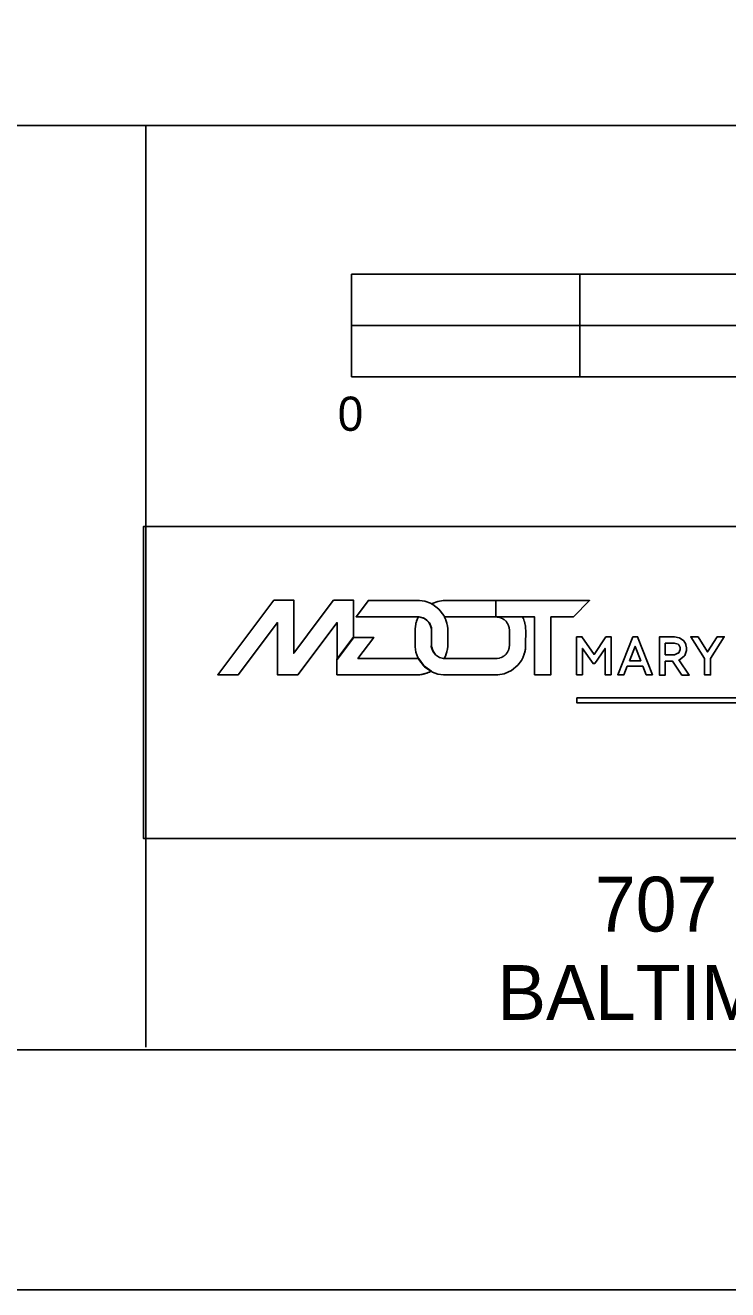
# Model space of a CAD drawing. Extents: x -1 to 9.2, y 0 to 14.8.
# Drawn here: x 2.774 to 3.799, y 0 to 1.846 of the extents above; entities that cross this region are included whole.
import ezdxf

# ---------------------------------------------------------------- set-up
doc = ezdxf.new("R2010")
doc.units = 0
for name, color, linetype in [('BORD-LINE', 7, 'Continuous'), ('BORD-SCAL', 7, 'Continuous'), ('MSHA-LOGO', 7, 'Continuous'), ('USER-LINE', 7, 'Continuous'), ('USER-PAGE', 7, 'Continuous')]:
    doc.layers.add(name, color=color, linetype=linetype)

msp = doc.modelspace()

# ---------------------------------------------------------------- linework, layer by layer
at = {"layer": 'BORD-LINE'}
for p, q in [((0.35, 1.7), (8.15, 1.7)), ((2.95, 0.354), (2.95, 1.7))]:
    msp.add_line(p, q, dxfattribs=at)
msp.add_lwpolyline([(0.35, 0.8607), (0.35, 0.35), (8.15, 0.35), (8.15, 10.65), (0.35, 10.65), (0.35, 0.8607)], dxfattribs=at)
at = {"layer": 'BORD-SCAL'}
for p, q in [((3.25, 1.333), (3.25, 1.483)), ((5.25, 1.483), (3.25, 1.483)), ((5.25, 1.483), (3.25, 1.483)), ((3.583, 1.333), (3.583, 1.483)), ((4.25, 1.408), (3.25, 1.408)), ((5.25, 1.333), (3.25, 1.333)), ((5.25, 1.333), (3.25, 1.333))]:
    msp.add_line(p, q, dxfattribs=at)
for points in [[(3.583, 1.483), (3.917, 1.483), (3.917, 1.408), (3.583, 1.408)], [(3.25, 1.333), (3.583, 1.333), (3.583, 1.408), (3.25, 1.408)]]:
    msp.add_lwpolyline(points, close=True, dxfattribs=at)
at = {"layer": 'MSHA-LOGO'}
for points in [[(3.2291, 0.9203), (3.2529, 0.952), (3.2529, 1.0068), (3.224, 1.0068), (3.206, 0.9829), (3.1658, 0.9294), (3.1658, 1.0068), (3.1369, 1.0068), (3.055, 0.898), (3.0849, 0.898), (3.142, 0.974), (3.142, 0.898), (3.172, 0.898), (3.2291, 0.974)], [(3.3477, 0.9824), (3.3484, 0.9824), (3.3551, 0.9806), (3.3557, 0.9803), (3.3564, 0.9799), (3.3597, 0.9775), (3.3626, 0.9746), (3.363, 0.974), (3.3636, 0.9732), (3.3655, 0.9691), (3.3666, 0.9647), (3.3667, 0.9637), (3.3667, 0.9637), (3.3667, 0.9636), (3.3667, 0.9636), (3.3667, 0.9634), (3.3667, 0.9628), (3.3667, 0.9627), (3.3667, 0.942), (3.3667, 0.9418), (3.3667, 0.9413), (3.3667, 0.9411), (3.3667, 0.9411), (3.3667, 0.941), (3.3667, 0.941), (3.3667, 0.9405), (3.3665, 0.9395), (3.3665, 0.9392), (3.3668, 0.9375), (3.3687, 0.9325), (3.3728, 0.9271), (3.3787, 0.9232), (3.3841, 0.9215), (3.3853, 0.9214), (3.3855, 0.9218), (3.3857, 0.922), (3.3857, 0.922), (3.3858, 0.9224), (3.3876, 0.9262), (3.3878, 0.9266), (3.3879, 0.9271), (3.3892, 0.9312), (3.3893, 0.9316), (3.3893, 0.9319), (3.3898, 0.934), (3.3899, 0.9342), (3.39, 0.9348), (3.3906, 0.9403), (3.3906, 0.9422), (3.3906, 0.9624), (3.3906, 0.9644), (3.39, 0.9697), (3.3899, 0.9704), (3.3898, 0.9706), (3.3893, 0.9727), (3.3893, 0.9729), (3.3892, 0.9733), (3.3879, 0.9775), (3.3878, 0.9779), (3.3876, 0.9783), (3.3858, 0.9822), (3.3857, 0.9826), (3.3846, 0.9846), (3.3776, 0.9935), (3.3687, 1.0005), (3.3667, 1.0016), (3.3652, 1.0023), (3.3571, 1.0052), (3.3492, 1.0064), (3.3466, 1.0064), (3.2747, 1.0064), (3.2568, 0.9826), (3.3466, 0.9826), (3.3467, 0.9825), (3.3474, 0.9824)], [(3.3858, 0.9823), (3.3862, 0.9823), (3.3864, 0.9823), (3.4601, 0.9823), (3.4602, 0.9823), (3.4605, 0.9823), (3.4605, 0.9823), (3.4607, 0.9826), (3.4607, 1.0062), (3.4607, 1.0062), (3.4602, 1.0062), (3.4601, 1.0062), (3.3864, 1.0062), (3.3838, 1.0062), (3.3759, 1.0049), (3.3679, 1.0021), (3.3667, 1.0016), (3.3687, 1.0005), (3.3776, 0.9935), (3.3846, 0.9846), (3.3857, 0.9826)], [(3.4607, 1.0062), (3.4607, 0.9824), (3.5172, 0.9824), (3.5172, 0.898), (3.5409, 0.898), (3.5409, 0.9824), (3.5739, 0.9824), (3.5975, 1.0061), (3.5975, 1.0062)], [(3.3671, 0.9028), (3.367, 0.9028), (3.3668, 0.903), (3.3668, 0.903), (3.3658, 0.9035), (3.3568, 0.9102), (3.356, 0.911), (3.3552, 0.9118), (3.3487, 0.9207), (3.3481, 0.9217), (3.348, 0.9217), (3.3478, 0.9217), (3.3477, 0.9217), (3.3474, 0.9217), (3.3468, 0.9217), (3.3466, 0.9217), (3.2594, 0.9217), (3.2826, 0.9523), (3.2527, 0.9523), (3.2289, 0.9208), (3.2289, 0.8979), (3.3465, 0.8979), (3.3471, 0.8979), (3.349, 0.898), (3.3492, 0.898), (3.3498, 0.898), (3.3515, 0.8983), (3.3517, 0.8983), (3.3519, 0.8983), (3.3524, 0.8985), (3.3525, 0.8985), (3.3526, 0.8985), (3.354, 0.8987), (3.3542, 0.8988), (3.3544, 0.8988), (3.3549, 0.8989), (3.3551, 0.8989), (3.3552, 0.899), (3.3564, 0.8992), (3.3566, 0.8992), (3.3566, 0.8993), (3.3574, 0.8995), (3.3575, 0.8995), (3.3576, 0.8996), (3.3587, 0.8999), (3.3588, 0.9), (3.3589, 0.9), (3.3596, 0.9002), (3.3597, 0.9003), (3.3598, 0.9003), (3.361, 0.9007), (3.3611, 0.9007), (3.3612, 0.9008), (3.3619, 0.901), (3.362, 0.901), (3.3621, 0.9011), (3.3634, 0.9016), (3.3635, 0.9016), (3.3636, 0.9017), (3.3642, 0.9019), (3.3642, 0.9019), (3.3644, 0.902), (3.3662, 0.9029), (3.3664, 0.903), (3.3665, 0.9029), (3.3669, 0.9028)], [(3.5784, 0.9534), (3.5862, 0.9534), (3.604, 0.9275), (3.6213, 0.9534), (3.6288, 0.9534), (3.6288, 0.8979), (3.6201, 0.8979), (3.6201, 0.9364), (3.6049, 0.9143), (3.6026, 0.9143), (3.587, 0.9364), (3.587, 0.8979), (3.5784, 0.8979)], [(3.6607, 0.9534), (3.6674, 0.9534), (3.6892, 0.8979), (3.68, 0.8979), (3.6751, 0.9102), (3.6524, 0.9102), (3.6475, 0.8979), (3.6386, 0.8979)], [(3.6993, 0.8976), (3.6993, 0.9531), (3.7189, 0.9531), (3.7213, 0.9531), (3.728, 0.9519), (3.7287, 0.9517), (3.7293, 0.9515), (3.7344, 0.9481), (3.7347, 0.9477), (3.7351, 0.9472), (3.7377, 0.9427), (3.7379, 0.9422), (3.738, 0.9417), (3.7388, 0.9371), (3.7388, 0.9356), (3.7388, 0.9331), (3.7364, 0.9262), (3.7359, 0.9255), (3.7354, 0.9248), (3.7287, 0.9197), (3.7278, 0.9195), (3.7428, 0.8973), (3.7321, 0.8973), (3.7186, 0.9177), (3.7079, 0.9177), (3.7079, 0.8973), (3.6993, 0.8973)], [(3.7079, 0.9442), (3.7079, 0.9272), (3.7192, 0.9272), (3.7211, 0.9272), (3.7264, 0.9292), (3.7269, 0.9295), (3.7274, 0.9299), (3.7298, 0.9346), (3.7298, 0.9361), (3.7298, 0.9377), (3.7277, 0.9418), (3.7272, 0.9422), (3.7268, 0.9425), (3.7209, 0.9442), (3.7189, 0.9442)], [(3.7739, 0.9217), (3.7739, 0.8976), (3.7652, 0.8976), (3.7652, 0.9217), (3.7451, 0.9534), (3.7557, 0.9534), (3.7696, 0.9313), (3.7837, 0.9534), (3.794, 0.9534)], [(3.6558, 0.9183), (3.6722, 0.9183), (3.6639, 0.9393)], [(3.5786, 0.8643), (5.4382, 0.8643), (5.4382, 0.8571), (3.5786, 0.8571)]]:
    msp.add_lwpolyline(points, close=True, dxfattribs=at)
for points in [[(3.3667, 0.9511), (3.3667, 0.9624), (3.3667, 0.9627), (3.3667, 0.9634), (3.3667, 0.9636), (3.3667, 0.964), (3.3668, 0.965), (3.3668, 0.9654), (3.3667, 0.9662), (3.3638, 0.9735), (3.3633, 0.9741), (3.3629, 0.9748), (3.36, 0.9778), (3.3566, 0.9802), (3.3558, 0.9806), (3.3552, 0.9809), (3.3485, 0.9827), (3.3478, 0.9827), (3.3478, 0.9826), (3.3477, 0.9824), (3.3474, 0.9818), (3.345, 0.9759), (3.3448, 0.9753), (3.3447, 0.9751), (3.3441, 0.973), (3.3441, 0.9728), (3.3439, 0.9719), (3.3429, 0.9648), (3.3429, 0.9624), (3.3429, 0.9511), (3.3429, 0.9499)], [(3.5043, 0.9624), (3.5043, 0.963), (3.5041, 0.9647), (3.5041, 0.9649), (3.5041, 0.9651), (3.5041, 0.9657), (3.5041, 0.9661), (3.504, 0.9672), (3.504, 0.9675), (3.504, 0.9676), (3.504, 0.9679), (3.504, 0.9679), (3.504, 0.968), (3.504, 0.9682), (3.504, 0.9682), (3.5039, 0.9684), (3.5037, 0.9699), (3.5036, 0.9701), (3.5036, 0.9702), (3.5035, 0.9705), (3.5035, 0.9707), (3.5035, 0.9708), (3.5031, 0.9725), (3.5031, 0.9726), (3.5031, 0.9728), (3.5031, 0.9729), (3.503, 0.9731), (3.5024, 0.9754), (3.5023, 0.9756), (3.5022, 0.976), (3.5008, 0.9798), (3.5006, 0.9801), (3.5006, 0.9803), (3.4997, 0.9822), (3.4996, 0.9824), (3.4996, 0.9825), (3.4994, 0.9827), (3.4613, 0.9827), (3.4612, 0.9824), (3.4616, 0.9824), (3.4618, 0.9824), (3.4619, 0.9824), (3.4624, 0.9823), (3.4625, 0.9823), (3.4628, 0.9822), (3.4659, 0.9816), (3.4661, 0.9815), (3.4664, 0.9814), (3.4689, 0.9806), (3.4691, 0.9805), (3.4693, 0.9804), (3.4706, 0.9796), (3.4708, 0.9796), (3.4709, 0.9796), (3.4709, 0.9796), (3.4711, 0.9795), (3.4723, 0.9787), (3.4725, 0.9786), (3.4726, 0.9785), (3.4726, 0.9785), (3.4727, 0.9784), (3.4738, 0.9776), (3.474, 0.9774), (3.4741, 0.9773), (3.4742, 0.9772), (3.4751, 0.9763), (3.4752, 0.9762), (3.4753, 0.9761), (3.4753, 0.9761), (3.4755, 0.9759), (3.4755, 0.9759), (3.4762, 0.9751), (3.4762, 0.975), (3.4764, 0.9749), (3.4764, 0.9748), (3.4766, 0.9745), (3.4767, 0.9744), (3.4767, 0.9744), (3.4774, 0.9734), (3.4774, 0.9734), (3.4775, 0.9733), (3.4777, 0.9728), (3.4777, 0.9728), (3.4778, 0.9726), (3.4779, 0.9726), (3.4779, 0.9725), (3.4783, 0.9718), (3.4783, 0.9717), (3.4784, 0.9716), (3.4786, 0.971), (3.4786, 0.971), (3.4787, 0.9709), (3.479, 0.97), (3.4791, 0.9699), (3.4791, 0.9699), (3.4792, 0.9693), (3.4792, 0.9692), (3.4793, 0.969), (3.4794, 0.969), (3.4794, 0.9689), (3.4797, 0.9683), (3.4797, 0.9681), (3.4797, 0.968), (3.4799, 0.9671), (3.48, 0.967), (3.48, 0.9668), (3.4801, 0.9663), (3.4801, 0.9661), (3.4802, 0.966), (3.4803, 0.9652), (3.4803, 0.9649), (3.4803, 0.9647), (3.4804, 0.9643), (3.4804, 0.9642), (3.4804, 0.9637), (3.4806, 0.9626), (3.4806, 0.9622), (3.4806, 0.9416), (3.4806, 0.9411), (3.4805, 0.9398), (3.4804, 0.9396), (3.4804, 0.9394), (3.4803, 0.9389), (3.4803, 0.9389), (3.4803, 0.9386), (3.4801, 0.9379), (3.4801, 0.9377), (3.4801, 0.9374), (3.48, 0.9369), (3.48, 0.9368), (3.4799, 0.9367), (3.4797, 0.9358), (3.4797, 0.9357), (3.4797, 0.9356), (3.4794, 0.9349), (3.4794, 0.9348), (3.4794, 0.9347), (3.4793, 0.9345), (3.4792, 0.9345), (3.4791, 0.934), (3.4791, 0.9339), (3.479, 0.9338), (3.4787, 0.933), (3.4786, 0.9328), (3.4786, 0.9328), (3.4784, 0.9322), (3.4783, 0.9321), (3.4783, 0.932), (3.4779, 0.9312), (3.4779, 0.9312), (3.4778, 0.931), (3.4777, 0.931), (3.4777, 0.931), (3.4775, 0.9305), (3.4774, 0.9304), (3.4774, 0.9303), (3.4767, 0.9294), (3.4767, 0.9294), (3.4766, 0.9293), (3.4764, 0.929), (3.4764, 0.9289), (3.4762, 0.9288), (3.4761, 0.9287), (3.4755, 0.9279), (3.4755, 0.9279), (3.4753, 0.9277), (3.4752, 0.9276), (3.4752, 0.9276), (3.4751, 0.9275), (3.4742, 0.9266), (3.4741, 0.9265), (3.474, 0.9264), (3.4738, 0.9263), (3.4727, 0.9254), (3.4726, 0.9253), (3.4725, 0.9252), (3.4725, 0.9251), (3.4723, 0.9251), (3.4711, 0.9243), (3.4709, 0.9242), (3.4708, 0.9242), (3.4708, 0.9242), (3.4707, 0.9242), (3.4693, 0.9234), (3.4691, 0.9233), (3.4689, 0.9232), (3.4664, 0.9224), (3.4661, 0.9223), (3.4658, 0.9222), (3.4628, 0.9216), (3.4625, 0.9215), (3.4623, 0.9215), (3.4618, 0.9214), (3.4618, 0.9214), (3.4615, 0.9214), (3.4609, 0.9214), (3.4607, 0.9214), (3.387, 0.9214), (3.3867, 0.9214), (3.3861, 0.9214), (3.386, 0.9214), (3.3841, 0.9215), (3.3787, 0.9232), (3.3728, 0.9272), (3.3687, 0.9331), (3.3671, 0.9384), (3.367, 0.9402), (3.367, 0.9405), (3.367, 0.9412), (3.367, 0.9414), (3.367, 0.9511), (3.3667, 0.9511)], [(3.3429, 0.9499), (3.3429, 0.9414), (3.3429, 0.9388), (3.3441, 0.931), (3.3469, 0.9229), (3.3477, 0.9214), (3.3482, 0.9204), (3.3549, 0.9112), (3.3557, 0.9104), (3.3564, 0.9096), (3.3656, 0.9029), (3.3667, 0.9024), (3.3682, 0.9016), (3.3762, 0.8988), (3.3841, 0.8976), (3.3867, 0.8976), (3.4604, 0.8976), (3.4635, 0.8976), (3.4726, 0.8993), (3.4835, 0.9042), (3.4926, 0.9117), (3.4981, 0.9188), (3.4994, 0.9214), (3.4995, 0.9216), (3.5004, 0.9234), (3.5005, 0.9236), (3.5006, 0.924), (3.502, 0.9278), (3.5021, 0.9282), (3.5022, 0.9284), (3.5029, 0.9307), (3.5029, 0.9309), (3.5029, 0.931), (3.5029, 0.9312), (3.5029, 0.9313), (3.5033, 0.933), (3.5033, 0.9331), (3.5033, 0.9333), (3.5035, 0.9336), (3.5035, 0.9337), (3.5035, 0.9339), (3.5038, 0.9354), (3.5038, 0.9355), (3.5038, 0.9356), (3.5038, 0.9358), (3.5038, 0.9358), (3.5038, 0.936), (3.5038, 0.9362), (3.5038, 0.9363), (3.5038, 0.9368), (3.504, 0.9378), (3.504, 0.9381), (3.504, 0.9387), (3.504, 0.9389), (3.504, 0.9395), (3.5041, 0.9409), (3.5041, 0.9414), (3.5043, 0.9624)]]:
    msp.add_lwpolyline(points, dxfattribs=at)
at = {"layer": 'USER-LINE'}
msp.add_lwpolyline([(5.5468, 0.6588), (2.9468, 0.6588), (2.9468, 1.1144), (5.5468, 1.1144)], close=True, dxfattribs=at)
at = {"layer": 'USER-PAGE'}
msp.add_lwpolyline([(0, 11), (8.5, 11), (8.5, 0), (0, 0)], close=True, dxfattribs=at)

# ---------------------------------------------------------------- texts
at = {"layer": 'BORD-LINE'}
for s, p in [('707 NORTH CALVERT ST.', (3.6052, 0.523)), ('BALTIMORE, MARYLAND 21202', (3.4626, 0.394))]:
    msp.add_text(s, height=0.079998, dxfattribs=at).set_placement(p)
at = {"layer": 'BORD-SCAL'}
msp.add_text('0', height=0.05, dxfattribs=at).set_placement((3.23, 1.254))

doc.saveas('drawing.dxf')
